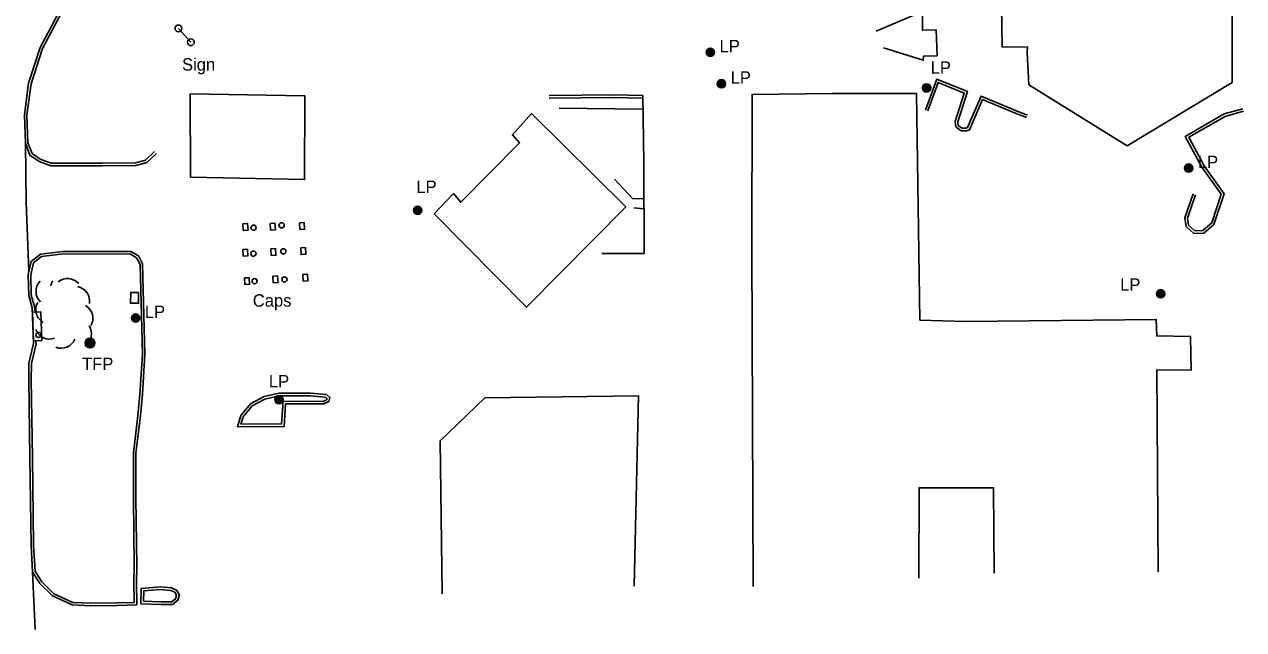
# Model space of a CAD drawing. Extents: x 2402803 to 2427059, y 6985292 to 6997652.
# Drawn here: x 2426586.9 to 2427059.3, y 6990907.1 to 6991141.5 of the extents above; entities that cross this region are included whole.
import ezdxf

# ---------------------------------------------------------------- set-up
doc = ezdxf.new("R2010")
doc.units = 0
for name, color, linetype in [('p_dtm sidewalk', 7, 'Continuous'), ('p_road - paved curb', 7, 'Continuous'), ('p_road bridge end', 7, 'Continuous'), ('p_structure building', 7, 'Continuous'), ('p_structure general', 7, 'Continuous'), ('p_structure sign', 7, 'Continuous'), ('p_utility manhole', 7, 'Continuous'), ('p_veg woods', 7, 'Continuous')]:
    doc.layers.add(name, color=color, linetype=linetype)

msp = doc.modelspace()

# ---------------------------------------------------------------- linework, layer by layer
at = {"layer": 'p_dtm sidewalk'}
for points in [[(2426916.9, 6991138.89), (2426934.89, 6991146.51), (2426934.84, 6991139.28), (2426940.18, 6991139.42), (2426940.6, 6991129.38), (2426935.26, 6991129.19), (2426935.19, 6991127.67), (2426919.78, 6991132.5)], [(2426826.55, 6991108.64), (2426794.14, 6991109.05)], [(2426826.92, 6991074.04), (2426822.6, 6991074), (2426815.49, 6991081.55)], [(2426826.94, 6991070.1), (2426823.07, 6991070.42)], [(2426630.13, 6990975.45), (2426630.13, 6990975.45)]]:
    msp.add_lwpolyline(points, dxfattribs=at)
at = {"layer": 'p_road - paved curb'}
for points in [[(2426601.73, 6991149.07), (2426592.98, 6991132.61), (2426588.48, 6991118.74), (2426586.88, 6991106.45), (2426587.28, 6991095.48), (2426589.02, 6991090.91), (2426592.59, 6991088.37), (2426597.15, 6991086.8), (2426617.17, 6991086.76), (2426630.12, 6991086.87), (2426634.3, 6991088.03), (2426638.02, 6991091.56)], [(2426602.57, 6991148.52), (2426593.9, 6991132.22), (2426589.46, 6991118.52), (2426587.88, 6991106.4), (2426588.27, 6991095.68), (2426589.85, 6991091.55), (2426593.05, 6991089.27), (2426597.32, 6991087.8), (2426617.17, 6991087.76), (2426629.98, 6991087.87), (2426633.79, 6991088.93), (2426637.33, 6991092.29)], [(2426936.07, 6991108.33), (2426940.45, 6991120.37), (2426952.29, 6991115.52), (2426948.58, 6991103.78), (2426948.71, 6991102.43), (2426950.25, 6991101.3), (2426951.67, 6991101.35), (2426952.39, 6991101.54), (2426957.58, 6991113.76), (2426971.58, 6991107.96), (2426975.58, 6991106.34)], [(2426937.01, 6991107.99), (2426941.03, 6991119.05), (2426951.06, 6991114.94), (2426947.56, 6991103.89), (2426947.76, 6991101.89), (2426949.94, 6991100.29), (2426951.82, 6991100.35), (2426953.12, 6991100.71), (2426958.11, 6991112.46), (2426971.2, 6991107.03), (2426975.21, 6991105.41)], [(2426826.47, 6991113.94), (2426815.26, 6991114.23), (2426790.21, 6991114.02)], [(2426826.44, 6991112.94), (2426815.25, 6991113.23), (2426790.22, 6991113.02)], [(2426810.68, 6991052.78), (2426827.02, 6991052.85), (2426826.86, 6991088.02), (2426826.47, 6991113.94)], [(2427039.76, 6991075.88), (2427036.54, 6991066.58), (2427037.01, 6991063.31), (2427040.1, 6991060.5), (2427043.9, 6991060.67), (2427047.84, 6991064.04), (2427051.73, 6991075.94), (2427044.01, 6991086.79), (2427038.08, 6991097.79), (2427052.23, 6991105.9), (2427059.33, 6991107.9)], [(2427040.7, 6991075.55), (2427037.56, 6991066.48), (2427037.95, 6991063.81), (2427040.47, 6991061.52), (2427043.51, 6991061.65), (2427046.98, 6991064.62), (2427050.62, 6991075.77), (2427043.16, 6991086.26), (2427036.74, 6991098.17), (2427051.84, 6991106.83), (2427059.06, 6991108.86)], [(2426588.65, 6991046.08), (2426587.61, 6991072.54), (2426587.28, 6991095.54)], [(2426630.11, 6990958), (2426630.1, 6990975.42), (2426631.89, 6990989.93), (2426632.6, 6990998.28), (2426633.61, 6991013.78), (2426632.69, 6991048.73), (2426631.07, 6991051.86), (2426628.08, 6991053.61), (2426624.48, 6991053.54), (2426601.94, 6991053.61), (2426593.16, 6991052.56), (2426589.47, 6991049.7), (2426588.41, 6991044.65), (2426588.54, 6991036.47), (2426589.92, 6991031.73), (2426590.41, 6991017.86), (2426588.66, 6991010.25), (2426588.56, 6991003.9), (2426589.02, 6990973.7), (2426589.46, 6990939.69), (2426590.03, 6990929.45), (2426592.82, 6990925.01), (2426597.77, 6990920.15), (2426605.38, 6990916.64), (2426612.57, 6990916.28), (2426622.69, 6990916.45), (2426630.39, 6990916.65), (2426630.32, 6990925.28), (2426630.47, 6990931.66)], [(2426629.11, 6990958), (2426629.1, 6990975.48), (2426630.9, 6990990.03), (2426631.6, 6990998.35), (2426632.61, 6991013.8), (2426631.7, 6991048.47), (2426630.31, 6991051.14), (2426627.82, 6991052.6), (2426624.49, 6991052.54), (2426602, 6991052.61), (2426593.55, 6991051.6), (2426590.37, 6991049.13), (2426589.41, 6991044.55), (2426589.54, 6991036.62), (2426590.91, 6991031.89), (2426590.95, 6991030.56)], [(2426591.38, 6991018.73), (2426591.41, 6991017.76), (2426589.66, 6991010.13), (2426589.56, 6991003.9), (2426590.02, 6990973.71), (2426590.46, 6990939.72), (2426591.01, 6990929.76), (2426593.6, 6990925.64), (2426598.35, 6990920.99), (2426605.62, 6990917.63), (2426612.59, 6990917.28), (2426622.67, 6990917.45), (2426629.38, 6990917.62), (2426629.32, 6990925.29), (2426629.47, 6990931.68)], [(2426685.44, 6990998.63), (2426679.76, 6990997.35), (2426674.53, 6990994.59), (2426670.76, 6990989.99), (2426669.42, 6990985.68), (2426687.5, 6990985.79), (2426688.04, 6990994.53), (2426702.94, 6990994.51), (2426704.89, 6990995.47), (2426705.24, 6990996.98), (2426703.93, 6990998.12), (2426697.75, 6990998.67)], [(2426697.75, 6990998.67), (2426685.44, 6990998.63)], [(2426685.66, 6990997.65), (2426680.11, 6990996.4), (2426675.18, 6990993.8), (2426671.66, 6990989.51), (2426670.78, 6990986.69), (2426686.56, 6990986.78), (2426687.1, 6990995.53), (2426702.71, 6990995.51), (2426704.02, 6990996.16), (2426704.13, 6990996.62), (2426703.52, 6990997.15), (2426697.66, 6990997.67)], [(2426697.75, 6990997.67), (2426685.44, 6990997.63)], [(2426629.47, 6990931.65), (2426629.11, 6990957.99)], [(2426630.47, 6990931.66), (2426630.11, 6990958)], [(2426590.03, 6990929.45), (2426591.08, 6990907.09)], [(2426639.57, 6990923.66), (2426632.12, 6990923.06), (2426632.03, 6990917.13), (2426639.84, 6990916.86)], [(2426639.84, 6990916.86), (2426644.33, 6990916.78), (2426646.38, 6990918.44), (2426646.93, 6990920.52), (2426645.86, 6990922.38), (2426643.9, 6990923.25), (2426639.57, 6990923.66)], [(2426639.65, 6990922.66), (2426633.11, 6990922.14), (2426633.04, 6990918.1), (2426639.87, 6990917.86)], [(2426639.86, 6990917.86), (2426643.98, 6990917.79), (2426645.5, 6990919.01), (2426645.86, 6990920.38), (2426645.16, 6990921.6), (2426643.64, 6990922.27), (2426639.48, 6990922.66)]]:
    msp.add_lwpolyline(points, dxfattribs=at)
at = {"layer": 'p_road bridge end'}
msp.add_lwpolyline([(2426590.08, 6991030.02), (2426590.47, 6991019.02), (2426593.68, 6991019.13), (2426593.29, 6991030.13)], close=True, dxfattribs=at)
at = {"layer": 'p_structure building'}
for points in [[(2426974.73, 6991163.37), (2427014.65, 6991186.78), (2427054.86, 6991163.99), (2427054.9, 6991119.06), (2427014.24, 6991094.54), (2426976.04, 6991118.17), (2426975.5, 6991130.63), (2426975.55, 6991132.85), (2426965.76, 6991132.74), (2426965.51, 6991148.48), (2426974.92, 6991147.99)], [(2426651.19, 6991082.3), (2426695.48, 6991081.43), (2426695.55, 6991113.9), (2426651.11, 6991114.61)], [(2426745.66, 6991068.09), (2426781.43, 6991031.95), (2426819.89, 6991070.89), (2426783.42, 6991106.99), (2426775.97, 6991098.8), (2426778.74, 6991095.68), (2426755.97, 6991072.65), (2426753.12, 6991076)]]:
    msp.add_lwpolyline(points, close=True, dxfattribs=at)
for points in [[(2426869.24, 6990923.74), (2426868.74, 6991054.42), (2426868.88, 6991114.39), (2426899.89, 6991114.72), (2426932.51, 6991114.71), (2426933.89, 6991026.98), (2426951.71, 6991026.42), (2427025.49, 6991027.23), (2427025.64, 6991020.87), (2427038.77, 6991020.67), (2427039.05, 6991007.54), (2427025.73, 6991007.77), (2427026.2, 6990929.49)], [(2426748.77, 6990921), (2426747.97, 6990980.27), (2426765.3, 6990996.84), (2426824.8, 6990997.71), (2426823.16, 6990923.88)], [(2426962.71, 6990928.97), (2426962.4, 6990962.04), (2426933.58, 6990962.07), (2426933.54, 6990926.98)]]:
    msp.add_lwpolyline(points, dxfattribs=at)
at = {"layer": 'p_structure general'}
msp.add_lwpolyline([(2426631.14, 6991037.7), (2426631.1, 6991033.51), (2426628.06, 6991033.54), (2426628.1, 6991037.73)], close=True, dxfattribs=at)
for centre in [(2426686.58, 6991063.71), (2426675.67, 6991062.79), (2426675.64, 6991052.73), (2426687.23, 6991053.62), (2426676.09, 6991042.1), (2426687.65, 6991042.73), (2426592.31, 6991021.24)]:
    msp.add_circle(centre, 1, dxfattribs=at)
at = {"layer": 'p_structure sign'}
msp.add_line((2426646.55, 6991140), (2426651.41, 6991134.61), dxfattribs=at)
for centre in [(2426646.56, 6991140), (2426651.42, 6991134.61)]:
    msp.add_circle(centre, 1.3, dxfattribs=at)
at = {"layer": 'p_utility manhole'}
for points in [[(2426693.46, 6991064.65), (2426695.29, 6991064.77), (2426695.46, 6991062.21), (2426693.63, 6991062.09)], [(2426671.54, 6991064.3), (2426673.37, 6991064.42), (2426673.54, 6991061.86), (2426671.71, 6991061.74)], [(2426682.13, 6991064.44), (2426683.96, 6991064.56), (2426684.13, 6991062), (2426682.3, 6991061.88)], [(2426671.48, 6991054.32), (2426673.31, 6991054.44), (2426673.48, 6991051.88), (2426671.65, 6991051.76)], [(2426682.36, 6991054.57), (2426684.19, 6991054.69), (2426684.36, 6991052.13), (2426682.53, 6991052.01)], [(2426693.94, 6991054.95), (2426695.77, 6991055.07), (2426695.94, 6991052.51), (2426694.11, 6991052.39)], [(2426672.15, 6991043.3), (2426673.98, 6991043.42), (2426674.15, 6991040.86), (2426672.32, 6991040.74)], [(2426683.17, 6991043.99), (2426685, 6991044.11), (2426685.17, 6991041.55), (2426683.34, 6991041.43)], [(2426694.76, 6991044.6), (2426696.59, 6991044.72), (2426696.76, 6991042.16), (2426694.93, 6991042.04)]]:
    msp.add_lwpolyline(points, close=True, dxfattribs=at)
for centre, radius in [((2426852.7, 6991130.73), 1.6), ((2426852.7, 6991130.73), 1.3), ((2426852.7, 6991130.73), 1), ((2426852.7, 6991130.73), 0.539), ((2426852.7, 6991130.73), 0.192), ((2426856.98, 6991118.54), 1.6), ((2426856.98, 6991118.54), 1.3), ((2426856.98, 6991118.54), 1), ((2426856.98, 6991118.54), 0.539), ((2426856.98, 6991118.54), 0.192), ((2426936.48, 6991116.95), 1.6), ((2426936.48, 6991116.95), 1.3), ((2426936.48, 6991116.95), 1), ((2426936.48, 6991116.95), 0.539), ((2426936.48, 6991116.95), 0.192), ((2427038.03, 6991085.86), 1.6), ((2427038.03, 6991085.86), 1.3), ((2427038.03, 6991085.86), 1), ((2427038.03, 6991085.86), 0.539), ((2427038.03, 6991085.86), 0.192), ((2426739.27, 6991069.53), 1.6), ((2426739.27, 6991069.53), 1.3), ((2426739.27, 6991069.53), 1), ((2426739.27, 6991069.53), 0.539), ((2426739.27, 6991069.53), 0.192), ((2427027.19, 6991037.18), 1.6), ((2427027.19, 6991037.18), 1.3), ((2427027.19, 6991037.18), 1), ((2427027.19, 6991037.18), 0.539), ((2427027.19, 6991037.18), 0.192), ((2426629.98, 6991027.83), 1.6), ((2426629.98, 6991027.83), 1.3), ((2426629.98, 6991027.83), 1), ((2426629.98, 6991027.83), 0.539), ((2426629.98, 6991027.83), 0.192), ((2426612.34, 6991018.13), 1.9), ((2426612.34, 6991018.13), 1.44), ((2426612.34, 6991018.13), 0.973), ((2426612.34, 6991018.13), 0.539), ((2426612.34, 6991018.13), 0.192), ((2426685.5, 6990996.19), 1.6), ((2426685.5, 6990996.19), 1.3), ((2426685.5, 6990996.19), 1), ((2426685.5, 6990996.19), 0.539), ((2426685.5, 6990996.19), 0.192)]:
    msp.add_circle(centre, radius, dxfattribs=at)
at = {"layer": 'p_veg woods'}
for centre, start, end in [((2426597.03, 6991038.1), 136.0619, 226.0619), ((2426602.77, 6991039.55), 151.3286, 172.3166), ((2426603.65, 6991037.45), 40.2799, 130.2799), ((2426606.51, 6991034.41), 349.9639, 79.9639), ((2426596.97, 6991030.99), 149.5408, 239.5408), ((2426607.77, 6991027.71), 330.4673, 60.4673), ((2426596.6, 6991025.27), 200.4639, 290.4639), ((2426607.24, 6991021.69), 303.5702, 33.5702), ((2426601.13, 6991021.71), 248.2872, 338.2872)]:
    msp.add_arc(centre, 5.65, start, end, dxfattribs=at)

# ---------------------------------------------------------------- texts
at = {"layer": 'p_structure general'}
msp.add_text('Caps', height=4.8, dxfattribs=at).set_placement((2426675.4, 6991032.19))
at = {"layer": 'p_structure sign'}
msp.add_text('Sign', height=4.8, dxfattribs=at).set_placement((2426647.97, 6991123.64))
at = {"layer": 'p_utility manhole'}
for s, p in [('  LP', (2426852.7, 6991130.73)), ('  LP', (2426934.49, 6991122.4)), ('  LP', (2426856.98, 6991118.54)), ('  LP', (2427038.03, 6991085.86)), ('  LP', (2426735.21, 6991076.26)), ('  LP', (2427007.92, 6991038.35)), ('  LP', (2426629.98, 6991027.83)), ('  TFP', (2426605.68, 6991007.63)), ('  LP', (2426678.07, 6991000.93))]:
    msp.add_text(s, height=4.8, dxfattribs=at).set_placement(p)

doc.saveas('drawing.dxf')
